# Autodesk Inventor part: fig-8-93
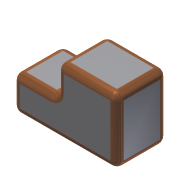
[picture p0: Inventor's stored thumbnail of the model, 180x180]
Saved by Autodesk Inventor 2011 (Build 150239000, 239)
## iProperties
Shininess: 64.0
Length Units: 11269
Angle Units: 11279
Time Units: 11290
Mass Units: 11283
Length Display Precision: 3
Angle Display Precision: 2
Compacted: True
Part Number: fig-8-93
Document SubType Name: Modeling
Created: 2002-12
Designer: deepak
Density: 1 g/cm^3
Density: 0.0
Volumn: 0.0
Area: 0.0
PropertySet Name: Model Information
Control State: 0
Master: False
Checked Out: False
Author: deepak
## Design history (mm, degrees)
sketch "Sketch1"
  geometry: L1 (-26.972, 23.346)-(8.906, 23.346); L2 (8.906, 23.346)-(8.906, 5.025); L3 (8.906, -15.84)-(-26.972, -15.84); L4 (-26.972, -15.84)-(-26.972, 23.346); L5 (8.906, -15.84)-(35.369, -15.84); L6 (35.369, -15.84)-(35.369, 5.025); L7 (35.369, 5.025)-(8.906, 5.025)
  constraints: 14 end point, 3 parallel, 2 horizontal, 2 perpendicular
extrude "Extrusion1" new body sketch "Sketch1" stored distance "d0" = 30; taper "d1" = 0 deg
fillet "Fillet1" dims "d2" = 4, "d3" = 4
body "Solid1"
